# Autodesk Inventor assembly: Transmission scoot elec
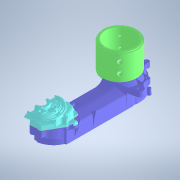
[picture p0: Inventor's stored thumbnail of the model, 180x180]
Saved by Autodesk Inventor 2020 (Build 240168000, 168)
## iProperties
Created: 2004-11
Part Number: Transmission scoot elec
Document SubType Name: Assembly
Designer: Bruno
Sending System: SolidWorks 2011
Last Author: Professeur
Last Saved: 2014-11-10
Author: Bruno
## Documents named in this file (5)
- D:\Téléchargements-2016-17\scoot_elec\Transmission scoot elec.iam
- D:\Téléchargements-2016-17\scoot_elec\Carter gauche.ipt
- D:\Téléchargements-2016-17\scoot_elec\Joint carter.ipt
- D:\Téléchargements-2016-17\scoot_elec\Carter droit.ipt
- D:\Téléchargements-2016-17\scoot_elec\pièces à assembler\Culasse moteur.ipt
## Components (4 placed, 4 different names)
1. Carter gauche:1 — Logement:1
2. JOINT CARTER:1
3. Carter droit:1
4. Culasse moteur:1 — Logement:1
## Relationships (1: Insert 1)
- Logement:1 [Insert]: Carter gauche:1 ↔ Culasse moteur:1
